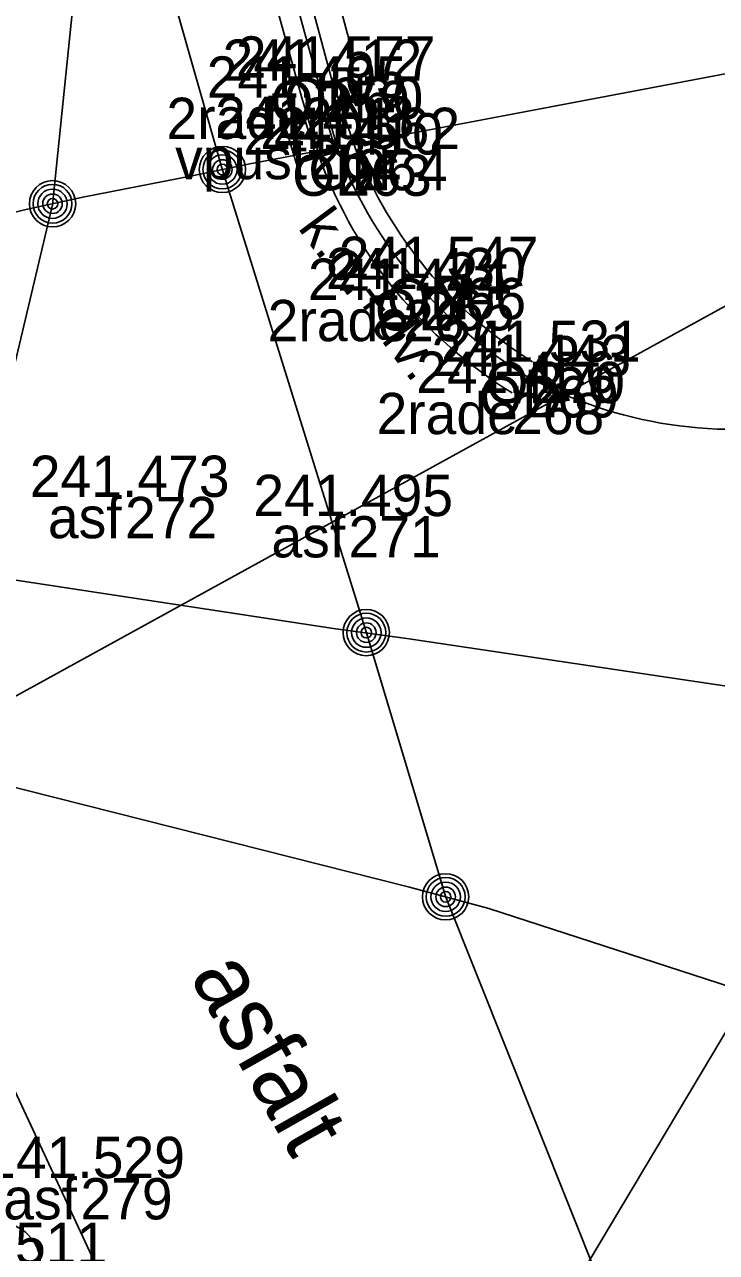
# Model space of a CAD drawing. Extents: x -599098 to -598820, y -1159597 to -1158744.
# Drawn here: x -598892.17 to -598883.79, y -1159366.05 to -1159351.19 of the extents above; entities that cross this region are included whole.
import ezdxf

# ---------------------------------------------------------------- set-up
doc = ezdxf.new("R2010")
doc.units = 0
for name, color, linetype in [('body', 7, 'Continuous'), ('dešťové vpusti šachty', 7, 'Continuous'), ('kresba', 7, 'Continuous'), ('kódy bodů', 7, 'Continuous'), ('popisy', 7, 'Continuous'), ('trol_detaily', 7, 'Continuous'), ('trol_převěsy', 7, 'Continuous'), ('trol_troljová stopa', 7, 'Continuous'), ('výšky bodů', 7, 'Continuous'), ('čísla bodů', 7, 'Continuous')]:
    doc.layers.add(name, color=color, linetype=linetype)

msp = doc.modelspace()

# ---------------------------------------------------------------- linework, layer by layer
at = {"layer": 'body'}
for p, q in [((-598888.458, -1159351.828), (-598888.458, -1159351.828)), ((-598888.619, -1159351.866), (-598888.619, -1159351.866)), ((-598888.81, -1159352.071), (-598888.81, -1159352.071)), ((-598888.709, -1159352.558), (-598888.709, -1159352.558)), ((-598888.161, -1159352.692), (-598888.161, -1159352.692)), ((-598888.355, -1159352.759), (-598888.355, -1159352.759)), ((-598887.353, -1159354.389), (-598887.353, -1159354.389)), ((-598887.212, -1159354.254), (-598887.212, -1159354.254)), ((-598887.585, -1159354.519), (-598887.585, -1159354.519)), ((-598886.018, -1159355.269), (-598886.018, -1159355.269)), ((-598886.092, -1159355.442), (-598886.092, -1159355.442)), ((-598886.267, -1159355.645), (-598886.267, -1159355.645)), ((-598890.951, -1159356.905), (-598890.951, -1159356.905)), ((-598888.246, -1159357.137), (-598888.246, -1159357.137)), ((-598891.491, -1159365.153), (-598891.491, -1159365.153))]:
    msp.add_line(p, q, dxfattribs=at)
at = {"layer": 'dešťové vpusti šachty'}
msp.add_line((-598888.781, -1159352.319), (-598888.637, -1159352.797), dxfattribs=at)
msp.add_lwpolyline([(-598889.021, -1159352.391), (-598888.876, -1159352.87), (-598888.397, -1159352.725), (-598888.542, -1159352.246)], close=True, dxfattribs=at)
msp.add_circle((-598892.475, -1159366.193), 0.5, dxfattribs=at)
at = {"layer": 'kresba'}
for p, q in [((-598890.79, -1159341.853), (-598888.18, -1159351.6)), ((-598888.619, -1159351.866), (-598889.392, -1159349.032)), ((-598888.458, -1159351.828), (-598889.212, -1159348.986)), ((-598889.639, -1159349.102), (-598888.81, -1159352.071)), ((-598888.458, -1159351.828), (-598888.161, -1159352.692)), ((-598888.619, -1159351.866), (-598888.355, -1159352.759)), ((-598888.81, -1159352.071), (-598888.586, -1159352.827))]:
    msp.add_line(p, q, dxfattribs=at)
for centre, radius, start, end in [((-598883.205, -1159350.75), 5.323, 201.3948, 238.0982), ((-598883.304, -1159350.843), 5.643, 200.593, 238.3279), ((-598883.227, -1159350.73), 5.515, 201.5899, 238.7026), ((-598883.578, -1159350.87), 5.217, 241.1907, 281.6482)]:
    msp.add_arc(centre, radius, start, end, dxfattribs=at)
at = {"layer": 'trol_detaily'}
for centre, radius in [((-598889.773, -1159352.94), 0.28), ((-598889.773, -1159352.94), 0.235), ((-598889.773, -1159352.94), 0.178), ((-598889.773, -1159352.94), 0.118), ((-598889.773, -1159352.94), 0.0641), ((-598891.828, -1159353.355), 0.28), ((-598891.828, -1159353.355), 0.235), ((-598891.828, -1159353.355), 0.178), ((-598891.828, -1159353.355), 0.118), ((-598891.828, -1159353.355), 0.0641), ((-598888.031, -1159358.548), 0.28), ((-598888.031, -1159358.548), 0.235), ((-598888.031, -1159358.548), 0.178), ((-598888.031, -1159358.548), 0.118), ((-598888.031, -1159358.548), 0.0641), ((-598887.071, -1159361.747), 0.28), ((-598887.071, -1159361.747), 0.235), ((-598887.071, -1159361.747), 0.178), ((-598887.071, -1159361.747), 0.118), ((-598887.071, -1159361.747), 0.0641)]:
    msp.add_circle(centre, radius, dxfattribs=at)
at = {"layer": 'trol_převěsy'}
for p, q in [((-598893.72, -1159360.11), (-598875.9, -1159350.31)), ((-598875.9, -1159350.31), (-598889.44, -1159352.87)), ((-598888.919, -1159372.178), (-598875.9, -1159350.31)), ((-598889.44, -1159352.87), (-598890.16, -1159353.02)), ((-598890.16, -1159353.02), (-598891.44, -1159353.27)), ((-598891.44, -1159353.27), (-598892.13, -1159353.42)), ((-598892.13, -1159353.42), (-598894.9, -1159354.08)), ((-598892.43, -1159357.89), (-598888.43, -1159358.5)), ((-598888.43, -1159358.5), (-598887.54, -1159358.62)), ((-598887.54, -1159358.62), (-598881.32, -1159359.55)), ((-598896.17, -1159359.44), (-598887.51, -1159361.63)), ((-598887.51, -1159361.63), (-598886.55, -1159361.89)), ((-598886.55, -1159361.89), (-598881.93, -1159363.39))]:
    msp.add_line(p, q, dxfattribs=at)
at = {"layer": 'trol_troljová stopa'}
for p, q in [((-598891.83, -1159353.37), (-598891.46, -1159349.76)), ((-598890.66, -1159349.82), (-598889.77, -1159352.95)), ((-598889.77, -1159352.95), (-598888.03, -1159358.55)), ((-598892.89, -1159357.84), (-598891.83, -1159353.37)), ((-598888.03, -1159358.55), (-598887.07, -1159361.75)), ((-598894.23, -1159359.93), (-598889.32, -1159370.45)), ((-598887.07, -1159361.75), (-598883.87, -1159369.77))]:
    msp.add_line(p, q, dxfattribs=at)

# ---------------------------------------------------------------- texts
at = {"layer": 'kódy bodů'}
for s, p in [('OD', (-598889.191, -1159352.366)), ('ON', (-598889.028, -1159352.328)), ('2rade', (-598890.45, -1159352.571)), ('vpust', (-598890.344, -1159353.058)), ('OD', (-598888.927, -1159353.259)), ('ON', (-598888.731, -1159353.192)), ('OD', (-598887.925, -1159354.889)), ('ON', (-598887.782, -1159354.754)), ('2rade', (-598889.225, -1159355.019)), ('ON', (-598886.588, -1159355.769)), ('OD', (-598886.664, -1159355.942)), ('2rade', (-598887.907, -1159356.145)), ('asf', (-598891.884, -1159357.405)), ('asf', (-598889.179, -1159357.637)), ('asf', (-598892.424, -1159365.653))]:
    msp.add_text(s, height=0.5, dxfattribs=at).set_placement(p)
at = {"layer": 'popisy'}
for s, height, rotation, p in [('k.o.+dv.', 0.5, 306.6092, (-598888.868, -1159353.646)), ('asfalt', 0.8, 299.495, (-598890.175, -1159362.709))]:
    msp.add_text(s, height=height, rotation=rotation, dxfattribs=at).set_placement(p)
at = {"layer": 'výšky bodů'}
for s, p in [('241.412', (-598889.771, -1159351.866)), ('241.577', (-598889.61, -1159351.828)), ('241.405', (-598889.962, -1159352.071)), ('241.413', (-598889.861, -1159352.558)), ('241.410', (-598889.521, -1159352.759)), ('241.562', (-598889.313, -1159352.692)), ('241.547', (-598888.364, -1159354.254)), ('241.430', (-598888.519, -1159354.389)), ('241.444', (-598888.737, -1159354.519)), ('241.531', (-598887.126, -1159355.269)), ('241.443', (-598887.244, -1159355.442)), ('241.456', (-598887.427, -1159355.645)), ('241.473', (-598892.103, -1159356.905)), ('241.495', (-598889.398, -1159357.137)), ('241.529', (-598892.643, -1159365.153)), ('241.511', (-598893.583, -1159366.193))]:
    msp.add_text(s, height=0.5, dxfattribs=at).set_placement(p)
at = {"layer": 'čísla bodů'}
for s, p in [('259', (-598888.619, -1159352.366)), ('260', (-598888.458, -1159352.328)), ('261', (-598888.81, -1159352.571)), ('262', (-598888.709, -1159353.058)), ('263', (-598888.355, -1159353.259)), ('264', (-598888.161, -1159353.192)), ('265', (-598887.353, -1159354.889)), ('266', (-598887.212, -1159354.754)), ('267', (-598887.585, -1159355.019)), ('270', (-598886.018, -1159355.769)), ('269', (-598886.092, -1159355.942)), ('268', (-598886.267, -1159356.145)), ('272', (-598890.951, -1159357.405)), ('271', (-598888.246, -1159357.637)), ('279', (-598891.491, -1159365.653))]:
    msp.add_text(s, height=0.5, dxfattribs=at).set_placement(p)

doc.saveas('drawing.dxf')
